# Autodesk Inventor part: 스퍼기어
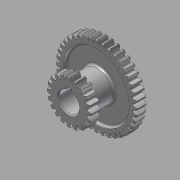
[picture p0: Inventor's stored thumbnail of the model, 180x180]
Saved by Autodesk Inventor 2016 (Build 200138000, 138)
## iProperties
Created: 2015-09
Part Number: 스퍼기어
Material: 강철, 연강
Document SubType Name: Modeling
Designer: mduedu
Density: 7.86 g/cm^3
Mass: 345.726 g
Surface Area: 225.641 cm^2
Volume: 43.9855 cm^3
Appearance: 강철
Author: mduedu
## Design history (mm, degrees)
sketch "스케치1"
  geometry: C1 r 38 at (0, 0); C2 r 40 at (0, 0); C3 r 35.5 at (0, 0); 1 further point
  constraints: 3 centre point, 3 coincident
  dimensions: "d0" = 76 diameter of C1; "d2" = 2 radial gap between concentric circles of C2 C1; "d3" = 71 diameter of C3 (computed from d0)
extrude "돌출1" new body sketch "스케치1" stored distance "d4" = 10; taper "d5" = 0 deg
sketch "스케치2"
  geometry: L1 (0, 35.5)-(0, -35.5); L2 (0, 0)-(40, 0); L3 (0, 0.57)-(39.996, 0.57); L4 (0, 1.57)-(39.969, 1.57); L5 (0, 2.07)-(39.946, 2.07); A1 r 35.5 centre (0, 0) between (0, 35.5) and (0, -35.5) reference; A2 r 40 centre (0, 0) between (40, 0) and (39.946, 2.07) reference; A3 r 9.234 centre (34.93, -7.149) between (39.996, 0.57) and (35.44, 2.07); A4 r 9.234 centre (34.93, 7.149) between (35.44, -2.07) and (39.996, -0.57); A5 r 40 centre (0, 0) between (39.996, -0.57) and (39.996, 0.57); A6 r 35.5 centre (0, 0) between (35.44, -2.07) and (35.44, 2.07); 4 further points
  constraints: 16 point on circle, 10 end point, 6 point on line, 4 centre point, 3 coincident, 3 parallel, 3 symmetric about line, 2 midpoint, 1 perpendicular, 1 vertical, 3 other
  dimensions: "d6" = 0.5 distance between parallel lines of L4 L5; "d8" = 1 distance between parallel lines of L3 L4; "d9" = 1.57 distance between parallel lines of L2 L4
extrude "돌출2" join sketch "스케치2" distance "d10" = 5; taper "d12" = 0 deg; dims "d11" = 5, "d13" = 0
fillet "모깎기1" dims "d17" = 0.5
chamfer "모따기1" distance "d21" = 1; stored, may be unused: second distance "d22" = 2, angle "d23" = 45 deg
sketch "스케치3"
  geometry: C1 r 32.5 at (0, 0); C2 r 15 at (0, 0); 1 further point
  constraints: 2 centre point, 2 coincident
  dimensions: "d27" = 65 diameter of C1; "d28" = 30 diameter of C2
extrude "돌출3" cut sketch "스케치3" distance "d29" = 3; taper "d30" = 0 deg
fillet "모깎기2" dims "d31" = 2
node "작업 평면2"
  node "작업 평면1"
sketch "스케치4"
  geometry: C1 r 15 at (0, 0) reference; 1 further point
extrude "돌출4" join sketch "스케치4" stored distance "d34" = 3; taper "d35" = 0 deg
sketch "스케치5"
  geometry: C1 r 17.5 at (0, 0); C2 r 20 at (0, 0); C3 r 22 at (0, 0); 1 further point
  constraints: 3 centre point, 3 coincident
  dimensions: "d36" = 40 diameter of C2; "d38" = 2 radial gap between concentric circles of C2 C3; "d39" = 35 diameter of C1 (= d36 - 2.5 x d38)
extrude "돌출6" join sketch "스케치5" distance "d46" = 10; taper "d47" = 0 deg
sketch "스케치6"
  geometry: L1 (0, 0)-(0, 22); L2 (-17.5, 0)-(17.5, 0); L3 (-0.57, 0)-(-0.57, 21.993); L4 (-1.57, 0)-(-1.57, 21.944); L5 (-2.07, 0)-(-2.07, 21.902); A1 r 22 centre (0, 0) between (0, 22) and (-0.57, 21.993) reference; A2 r 17.5 centre (0, 0) between (-17.5, 0) and (17.5, 0) reference; A3 r 9.431 centre (7.348, 16.868) between (-0.57, 21.993) and (-2.07, 17.377); A4 r 9.431 centre (-7.348, 16.868) between (2.07, 17.377) and (0.57, 21.993); A5 r 17.5 centre (0, 0) between (2.07, 17.377) and (-2.07, 17.377); A6 r 22 centre (0, 0) between (0.57, 21.993) and (-0.57, 21.993); 4 further points
  constraints: 16 point on circle, 10 end point, 5 point on line, 4 centre point, 3 coincident, 3 symmetric about line, 2 parallel, 2 perpendicular, 1 midpoint, 1 vertical, 3 other
  dimensions: "d40" = 0.5 distance between parallel lines of L4 L5; "d42" = 1 distance between parallel lines of L3 L4; "d43" = 1.57 distance between parallel lines of L1 L4
extrude "돌출5" join sketch "스케치6" distance "d44" = 10; taper "d45" = 0 deg
fillet "모깎기3" dims "d48" = 0.5
chamfer "모따기2" distance "d49" = 1; stored, may be unused: second distance "d50" = 2, angle "d51" = 45 deg
sketch "스케치7"
  geometry: C1 r 10 at (0, 0); 1 further point
  constraints: 1 centre point, 1 coincident
  dimensions: "d55" = 20 diameter of C1
extrude "돌출7" cut sketch "스케치7" stored distance "d56" = 10; taper "d57" = 0 deg
sketch "스케치8"
  geometry: L1 (-9.539, -3)-(-12.8, -3); L2 (-12.8, -3)-(-12.8, 3); L3 (-12.8, 3)-(-9.539, 3); L4 (-9.539, 3)-(-9.539, -3); A1 r 10 centre (0, 0) between (-9.539, -3) and (-9.539, 3) reference; 2 further points
  constraints: 8 end point, 3 point on circle, 2 parallel, 1 horizontal, 1 horizontal alignment, 1 perpendicular
  dimensions: "d58" = 6 distance of L1.end L2.end; "d60" = 22.8 distance from line of point (10, 0) L2
extrude "돌출8" cut sketch "스케치8" stored distance "d61" = 10; taper "d62" = 0 deg
chamfer "모따기3" distance "d63" = 1; stored, may be unused: second distance "d64" = 2, angle "d65" = 45 deg
fillet "모깎기4" dims "d66" = 2
node "솔리드1"
pattern_circular "원형 패턴3" dims "d25" = 360 deg
mirror "대칭1"
pattern_circular "원형 패턴4" dims "d53" = 360 deg
other parameters: "d32" = 5, "d33" = 42
